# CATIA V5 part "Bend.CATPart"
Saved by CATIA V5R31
Part number: Bend
Bounding box of the stored display mesh (mm): x -50 to 50, y -150 to 15, z -50 to 115
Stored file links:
  D:\PROJECTS\Project 2021\US EDITION\CATIA V5 6R 2021\Resources\Part Files\c12_catia_v5_6r2021_prt\c12_catia_v5-6r2021 figr_12-44\Bend.CATPart
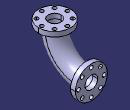
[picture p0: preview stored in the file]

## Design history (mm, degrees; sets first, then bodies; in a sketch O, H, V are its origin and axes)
Body1 (main body)
  Sketch1 on yz-plane, origin (0, 0, 0), H (0, 1, 0), V (0, 0, 1)
    arc A1 centre (0, 100) radius 100 from (-100, 100) to (0, 0) ccw
    point P1 (0, 100)
    coincidence: P1 V
  Sketch2 on zx-plane, origin (0, 0, 0), H (-1, 0, 0), V (0, 0, 1)
    circle A1 centre (0, 0) radius 30
    point P1 (0, -30)
    radius A1 = 30
    coincidence: A1 P1, P1 V
  Rib1: profile Sketch2, centre curve Sketch1
  Sketch3 on face of Rib1, origin (0, 0, 0), H (-1, 0, 0), V (0, 0, 1)
    circle A1 centre (0, 0) radius 50
    point P1 (0, -50)
    radius A1 = 50
    coincidence: A1 P1, P1 V
  Pad1: profile Sketch3, direction (0, 1, 0), length 15
  Sketch4 on face of Rib1, origin (0, 0, 100), H (1, 0, 0), V (0, 1, 0)
    circle A1 centre (0, -100) radius 50
    point P1 (0, -100)
    reference projected circle E1 centre (0, -100) radius 30 from edge [face of Rib1 | face of Rib1]
    radius A1 = 50
    coincidence: P1 V
    concentricity: A1 E1
  Pad2: profile Sketch4, direction (0, 0, 1), length 15
  Sketch5 on face of Pad1, origin (0, 15, 0), H (-1, 0, 0), V (0, 0, 1)
    circle A1 centre (0, 0) radius 20
    radius A1 = 20
  Sketch6 on yz-plane, origin (0, 0, 0), H (0, 1, 0), V (0, 0, 1)
    projected arc E1 centre (0, 100) radius 100 from (-100, 100) to (0, 0) ccw from edge of Sketch1
    line L1 (-100, 100) -> (-100, 115)
    point P3 (-100, 115)
    line L2 (0, 0) -> (15, 0)
    point P4 (15, 0)
    reference projected line E2 (15, 50) -> (15, -50) from edge [face of Pad1 | face of Pad1]
    reference projected line E3 (-50, 115) -> (-150, 115) from edge [face of Pad2 | face of Pad2]
    tangency: L1 E1, L2 E1
    coincidence: P4 E2, P3 E3
  Slot1: profile Sketch5, centre curve Sketch6
  Sketch7 on face of Pad1, origin (0, 15, 0), H (-1, 0, 0), V (0, 0, 1)
    circle A1 centre (0, -40) radius 6
    point P1 (0, -40)
    radius A1 = 6
    distance H P1 = 40
    coincidence: P1 V
  Pocket1: profile Sketch7, direction (0, -1, 0), length 15
  CircPattern1: of Pocket1, instances 8, angular step 45, axis from face of Pad1
  Sketch8 on face of Pad2, origin (0, 0, 115), H (1, 0, 0), V (0, 1, 0)
    circle A1 centre (0, -140) radius 6
    point P1 (0, -140)
    reference projected point E1 (0, -100) from vertex of Sketch1
    radius A1 = 6
    distance E1 P1 = 40
    coincidence: P1 V
  Pocket2: profile Sketch8, direction (0, 0, -1), length 15
  CircPattern2: of Pocket2, instances 8, angular step 45, axis from face of Pad2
